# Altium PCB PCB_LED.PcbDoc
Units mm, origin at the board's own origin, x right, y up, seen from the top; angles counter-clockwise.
Board outline 30 x 5 mm, 2 copper layers (Top Layer, Bottom Layer); 3 components, 0 nets, 6 pads, 0 vias.
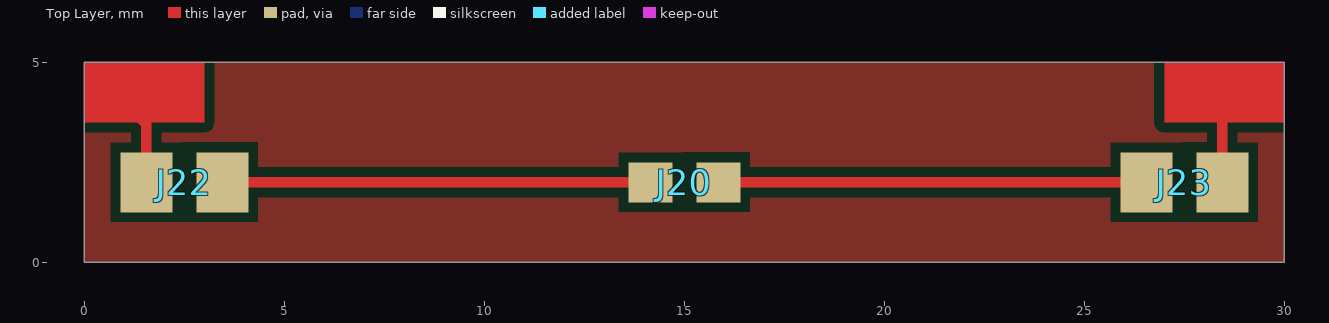
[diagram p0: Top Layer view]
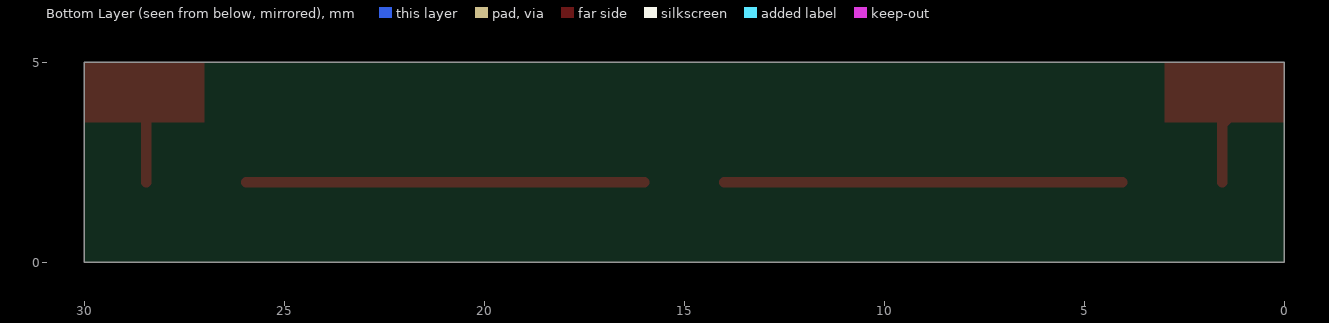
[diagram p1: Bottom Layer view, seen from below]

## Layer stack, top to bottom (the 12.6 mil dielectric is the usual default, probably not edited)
Top Solder: solder mask 0.0102, Solder Resist, Dk 3.5
Top Layer: signal copper 0.0356
Dielectric 1: dielectric 0.32, FR-4, Dk 4.8
Bottom Layer: signal copper 0.0356
Bottom Solder: solder mask 0.0102, Solder Resist, Dk 3.5

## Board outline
0,0 30,0 30,5 0,5

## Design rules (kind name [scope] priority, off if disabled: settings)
Clearance [All] p1: gap=0.254
PolygonConnect [All] p1: connectstyle=Relief reliefconductorwidth=0.254 reliefentries=4 polygonreliefangle="90 Angle" airgapwidth=0.254
RoutingVias [All] p1: holewidth=0.711 width=1.27 viastyle="Through Hole" minholewidth=0.711 minwidth=1.27 maxholewidth=0.711 maxwidth=1.27
SolderMaskExpansion [All] p1: expansion=0.102
Width [All] p1: maxlimit=0.254 minlimit=0.254 preferedwidth=0.254
29 further rules are at their usual default settings.

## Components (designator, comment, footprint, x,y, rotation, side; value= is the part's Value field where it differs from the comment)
J20 "Comment" 0603-2 15,2 r180 top
J22 "Comment" 0805-2 2.5,2 r180 top
J23 "Comment" 0805-2 27.5,2 r180 top

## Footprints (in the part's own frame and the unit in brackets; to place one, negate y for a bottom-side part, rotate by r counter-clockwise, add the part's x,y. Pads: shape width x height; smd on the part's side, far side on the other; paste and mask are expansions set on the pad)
0603-2 [mm] "贴片无丝印"
  rect 1.1x1 smd: 1(-0.85,0) 2(0.85,0)
0805-2 [mm] "贴片无丝印"
  rect 1.3x1.5 smd: 1(-0.95,0) 2(0.95,0)

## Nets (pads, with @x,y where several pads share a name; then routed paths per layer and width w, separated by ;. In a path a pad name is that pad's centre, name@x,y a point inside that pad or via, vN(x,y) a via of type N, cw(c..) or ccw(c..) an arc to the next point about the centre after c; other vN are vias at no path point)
pads on no net: J20.1 J20.2 J22.1 J22.2 J23.1 J23.2
copper on no net: | length 24.3
  Top Layer w0.254: 1,4 1.55,3.45 1.55,2 ; 4.05,2 14,2 ; 16,2 25.95,2 ; 28,4 28.45,3.55 28.45,2

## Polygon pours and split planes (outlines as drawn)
no net on Top Layer "Top Layer-No Net" (solid, pour order 3): 0,5 30,5 30,0 0,0 0,5

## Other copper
Top Layer:
  rectangle: 27,3.5 30,5
  rectangle: 0,3.5 3,5

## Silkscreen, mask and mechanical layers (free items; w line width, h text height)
Mechanical 1:
  the board outline again, w0.254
